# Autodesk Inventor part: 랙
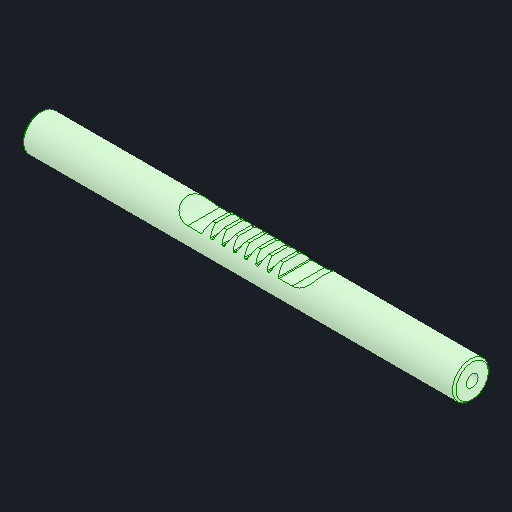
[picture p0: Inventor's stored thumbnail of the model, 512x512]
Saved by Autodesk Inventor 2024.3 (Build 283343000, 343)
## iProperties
Created: 2024-05
Part Number: 랙
Material: 강철, 탄소
Document SubType Name: Modeling
Designer: MyPc
Density: 7.85 g/cm^3
Appearance: 기본값
Author: jhkim
Sending System: Autodesk Inventor 2025
Preprocessor: ST-DEVELOPER v20
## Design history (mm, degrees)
node "랙1"
node "솔리드2"
node "솔리드1"
